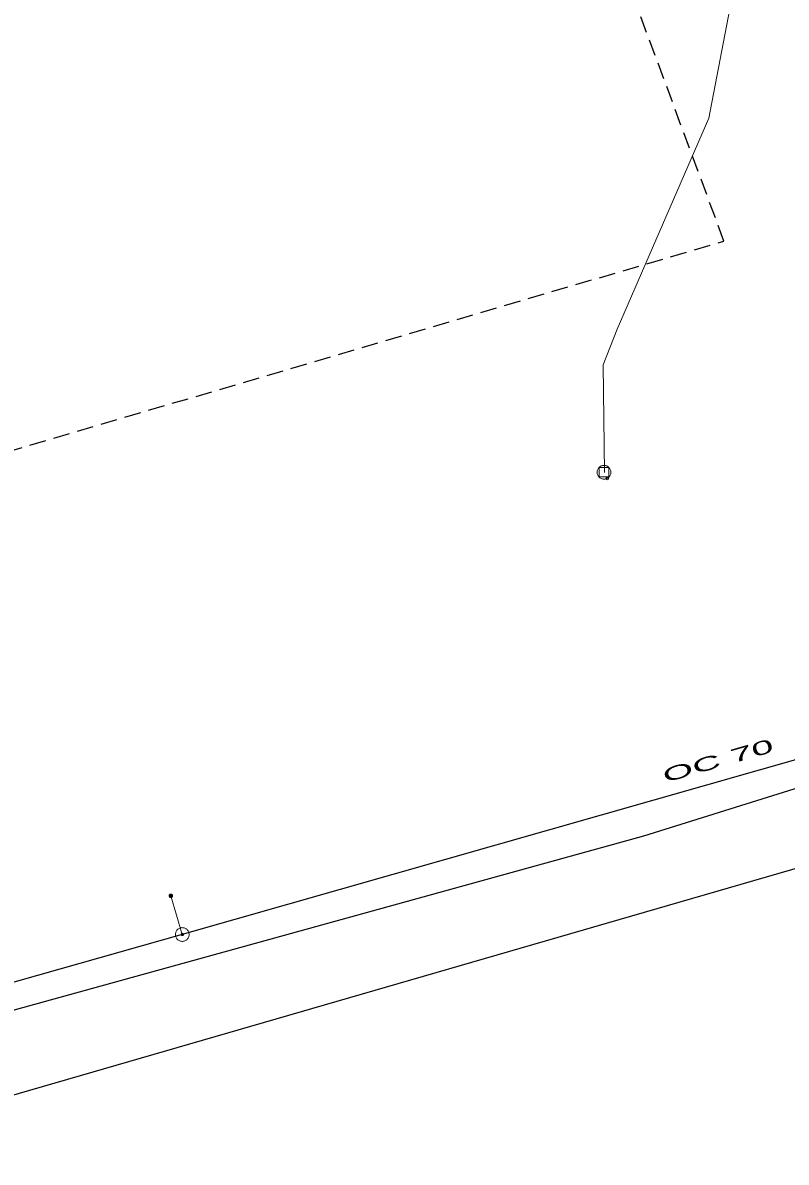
# Model space of a CAD drawing. Extents: x -690254 to -689100, y -975264 to -974703.
# Drawn here: x -689747.9 to -689692.3, y -975075.2 to -974992.3 of the extents above; entities that cross this region are included whole.
import ezdxf

# ---------------------------------------------------------------- set-up
doc = ezdxf.new("R2010")
doc.units = 0
doc.header["$LTSCALE"] = 0.4
doc.header["$PDMODE"] = 32
doc.header["$PDSIZE"] = 0.2
doc.linetypes.add('MEDIUM_DASHED', pattern=[4.5, 3, -1.5])
for name, color, linetype, lineweight in [('1', 7, 'Continuous', 13), ('11', 7, 'Continuous', 13), ('14', 7, 'Continuous', 13), ('17', 7, 'Continuous', 25), ('22', 7, 'Continuous', 13), ('47', 7, 'Continuous', 13), ('63', 7, 'MEDIUM_DASHED', 25), ('9', 7, 'Continuous', 13)]:
    doc.layers.add(name, color=color, linetype=linetype, lineweight=lineweight)

msp = doc.modelspace()

# ---------------------------------------------------------------- linework, layer by layer
at = {"layer": '11'}
msp.add_lwpolyline([(-689705.559, -975025.01), (-689705.649, -975017.17), (-689704.62, -975014.579), (-689697.949, -974999.219), (-689696.3, -974990.64)], dxfattribs=at)
at = {"layer": '14'}
msp.add_line((-689736.277, -975058.649), (-689737.109, -975055.829), dxfattribs=at)
at = {"layer": '17'}
for p, q in [((-689660.67, -975037.094), (-689736.277, -975058.649)), ((-689736.277, -975058.649), (-689791.401, -975074.243))]:
    msp.add_line(p, q, dxfattribs=at)
for points in [[(-689651.896, -975035.605), (-689702.719, -975051.484), (-689800.052, -975078.399), (-689860.597, -975095.177), (-689913.514, -975110.178), (-689937.55, -975117.079), (-689948.793, -975119.833), (-689957.109, -975122.39), (-689986.109, -975129.956), (-690002.122, -975134.99), (-690005.949, -975136.193), (-690003.879, -975142.529), (-690036.781, -975151.448), (-690069.227, -975161.229), (-690080.424, -975165.129), (-690111.773, -975174.27), (-690115.204, -975175.288), (-690118.142, -975167.265)], [(-689654.548, -975043.14), (-689663.456, -975045.689), (-689770.531, -975076.689), (-689789.368, -975082.372), (-689795.659, -975083.946), (-689875.347, -975106.869), (-689899.317, -975114.153), (-689955.443, -975128.986), (-689982.052, -975137.931), (-690059.236, -975159.265)]]:
    msp.add_lwpolyline(points, dxfattribs=at)
at = {"layer": '22'}
for points in [[(-689705.09, -975025.001), (-689705.092, -975024.949), (-689705.102, -975024.896), (-689705.115, -975024.846), (-689705.133, -975024.797), (-689705.157, -975024.751), (-689705.187, -975024.706), (-689705.219, -975024.666), (-689705.257, -975024.63), (-689705.296, -975024.596), (-689705.34, -975024.567), (-689705.388, -975024.543), (-689705.436, -975024.526), (-689705.486, -975024.511), (-689705.539, -975024.503), (-689705.59, -975024.502), (-689705.642, -975024.504), (-689705.695, -975024.513), (-689705.746, -975024.526), (-689705.794, -975024.544), (-689705.84, -975024.569), (-689705.884, -975024.598), (-689705.925, -975024.63), (-689705.962, -975024.668), (-689705.995, -975024.707), (-689706.023, -975024.751), (-689706.047, -975024.799), (-689706.066, -975024.847), (-689706.08, -975024.897), (-689706.086, -975024.95), (-689706.089, -975025.001), (-689706.086, -975025.053), (-689706.078, -975025.106), (-689706.066, -975025.157), (-689706.046, -975025.205), (-689706.022, -975025.251), (-689705.994, -975025.296), (-689705.961, -975025.336), (-689705.924, -975025.373), (-689705.883, -975025.406), (-689705.84, -975025.435), (-689705.792, -975025.458), (-689705.744, -975025.477), (-689705.693, -975025.491), (-689705.641, -975025.498), (-689705.59, -975025.501), (-689705.538, -975025.498), (-689705.485, -975025.489), (-689705.435, -975025.477), (-689705.386, -975025.457), (-689705.339, -975025.433), (-689705.295, -975025.405), (-689705.255, -975025.373), (-689705.219, -975025.335), (-689705.185, -975025.295), (-689705.156, -975025.251), (-689705.132, -975025.203), (-689705.114, -975025.156), (-689705.1, -975025.105), (-689705.092, -975025.052)], [(-689705.94, -975024.651), (-689705.232, -975024.65), (-689705.231, -975025.344), (-689705.94, -975025.344)]]:
    msp.add_lwpolyline(points, close=True, dxfattribs=at)
msp.add_point((-689705.365, -975025.449), dxfattribs=at)
at = {"layer": '47'}
for points in [[(-689735.794, -975058.519), (-689735.81, -975058.47), (-689735.831, -975058.422), (-689735.858, -975058.377), (-689735.888, -975058.334), (-689735.923, -975058.295), (-689735.962, -975058.26), (-689736.005, -975058.23), (-689736.05, -975058.204), (-689736.097, -975058.182), (-689736.147, -975058.166), (-689736.199, -975058.155), (-689736.251, -975058.15), (-689736.303, -975058.149), (-689736.355, -975058.155), (-689736.406, -975058.166), (-689736.455, -975058.182), (-689736.503, -975058.203), (-689736.549, -975058.23), (-689736.591, -975058.26), (-689736.63, -975058.295), (-689736.665, -975058.334), (-689736.696, -975058.377), (-689736.722, -975058.422), (-689736.744, -975058.469), (-689736.759, -975058.519), (-689736.77, -975058.571), (-689736.776, -975058.623), (-689736.776, -975058.675), (-689736.77, -975058.727), (-689736.759, -975058.778), (-689736.743, -975058.827), (-689736.722, -975058.875), (-689736.696, -975058.921), (-689736.665, -975058.963), (-689736.63, -975059.002), (-689736.592, -975059.037), (-689736.549, -975059.068), (-689736.504, -975059.095), (-689736.456, -975059.116), (-689736.406, -975059.131), (-689736.354, -975059.142), (-689736.303, -975059.148), (-689736.25, -975059.148), (-689736.198, -975059.142), (-689736.147, -975059.131), (-689736.098, -975059.115), (-689736.05, -975059.094), (-689736.005, -975059.068), (-689735.962, -975059.037), (-689735.923, -975059.002), (-689735.888, -975058.964), (-689735.858, -975058.921), (-689735.831, -975058.876), (-689735.81, -975058.828), (-689735.794, -975058.778), (-689735.783, -975058.726), (-689735.778, -975058.675), (-689735.777, -975058.622), (-689735.783, -975058.57)], [(-689736.197, -975058.627), (-689736.2, -975058.619), (-689736.204, -975058.611), (-689736.208, -975058.604), (-689736.213, -975058.597), (-689736.219, -975058.591), (-689736.225, -975058.585), (-689736.232, -975058.58), (-689736.239, -975058.575), (-689736.247, -975058.572), (-689736.255, -975058.569), (-689736.264, -975058.568), (-689736.273, -975058.567), (-689736.281, -975058.567), (-689736.289, -975058.567), (-689736.298, -975058.569), (-689736.306, -975058.572), (-689736.314, -975058.576), (-689736.321, -975058.58), (-689736.328, -975058.585), (-689736.334, -975058.591), (-689736.34, -975058.597), (-689736.345, -975058.604), (-689736.35, -975058.611), (-689736.354, -975058.619), (-689736.356, -975058.627), (-689736.357, -975058.636), (-689736.358, -975058.645), (-689736.358, -975058.653), (-689736.358, -975058.661), (-689736.356, -975058.67), (-689736.353, -975058.678), (-689736.349, -975058.686), (-689736.345, -975058.693), (-689736.34, -975058.7), (-689736.334, -975058.706), (-689736.329, -975058.712), (-689736.321, -975058.717), (-689736.314, -975058.722), (-689736.306, -975058.726), (-689736.298, -975058.728), (-689736.289, -975058.729), (-689736.28, -975058.73), (-689736.272, -975058.73), (-689736.264, -975058.73), (-689736.255, -975058.728), (-689736.247, -975058.725), (-689736.239, -975058.721), (-689736.232, -975058.717), (-689736.225, -975058.712), (-689736.219, -975058.706), (-689736.213, -975058.701), (-689736.208, -975058.693), (-689736.203, -975058.686), (-689736.2, -975058.678), (-689736.197, -975058.67), (-689736.196, -975058.661), (-689736.195, -975058.652), (-689736.195, -975058.644), (-689736.195, -975058.636)]]:
    msp.add_lwpolyline(points, close=True, dxfattribs=at)
at = {"layer": '63'}
msp.add_lwpolyline([(-690175.832, -975238.167), (-690201.511, -975156.663), (-690201.511, -975156.663), (-689696.859, -975008.171), (-689696.859, -975008.171), (-689730.354, -974917.735), (-689730.354, -974917.735), (-689127.452, -974763.66), (-689127.452, -974763.66), (-689118.52, -974838.465), (-689118.52, -974838.465), (-689624.288, -974970.21), (-689624.288, -974970.21), (-689593.026, -975070.694), (-689593.026, -975070.694)], close=True, dxfattribs=at)
at = {"layer": '9'}
for points in [[(-689737.235, -975055.829), (-689737.235, -975055.842), (-689737.233, -975055.855), (-689737.23, -975055.868), (-689737.225, -975055.88), (-689737.219, -975055.892), (-689737.212, -975055.903), (-689737.204, -975055.913), (-689737.194, -975055.923), (-689737.184, -975055.931), (-689737.173, -975055.938), (-689737.161, -975055.944), (-689737.149, -975055.949), (-689737.136, -975055.952), (-689737.123, -975055.954), (-689737.11, -975055.956), (-689737.097, -975055.955), (-689737.084, -975055.953), (-689737.071, -975055.95), (-689737.059, -975055.945), (-689737.047, -975055.939), (-689737.036, -975055.932), (-689737.026, -975055.924), (-689737.016, -975055.914), (-689737.008, -975055.904), (-689737.001, -975055.893), (-689736.995, -975055.881), (-689736.99, -975055.869), (-689736.987, -975055.856), (-689736.985, -975055.843), (-689736.983, -975055.83), (-689736.984, -975055.817), (-689736.986, -975055.804), (-689736.989, -975055.791), (-689736.994, -975055.779), (-689737, -975055.767), (-689737.007, -975055.756), (-689737.015, -975055.746), (-689737.025, -975055.736), (-689737.035, -975055.728), (-689737.046, -975055.721), (-689737.058, -975055.715), (-689737.07, -975055.71), (-689737.083, -975055.707), (-689737.096, -975055.705), (-689737.109, -975055.704), (-689737.122, -975055.704), (-689737.135, -975055.706), (-689737.148, -975055.709), (-689737.16, -975055.714), (-689737.172, -975055.72), (-689737.183, -975055.727), (-689737.193, -975055.735), (-689737.203, -975055.745), (-689737.211, -975055.755), (-689737.218, -975055.766), (-689737.224, -975055.778), (-689737.229, -975055.79), (-689737.232, -975055.803), (-689737.234, -975055.816)], [(-689737.215, -975055.829), (-689737.216, -975055.84), (-689737.214, -975055.851), (-689737.211, -975055.862), (-689737.207, -975055.872), (-689737.202, -975055.882), (-689737.196, -975055.891), (-689737.189, -975055.9), (-689737.181, -975055.908), (-689737.172, -975055.915), (-689737.163, -975055.921), (-689737.153, -975055.926), (-689737.143, -975055.93), (-689737.132, -975055.933), (-689737.121, -975055.936), (-689737.11, -975055.936), (-689737.099, -975055.936), (-689737.088, -975055.934), (-689737.077, -975055.931), (-689737.067, -975055.927), (-689737.057, -975055.922), (-689737.048, -975055.916), (-689737.039, -975055.909), (-689737.031, -975055.901), (-689737.024, -975055.892), (-689737.018, -975055.883), (-689737.013, -975055.873), (-689737.009, -975055.863), (-689737.006, -975055.852), (-689737.004, -975055.841), (-689737.003, -975055.83), (-689737.003, -975055.819), (-689737.005, -975055.808), (-689737.008, -975055.797), (-689737.012, -975055.787), (-689737.017, -975055.777), (-689737.023, -975055.768), (-689737.03, -975055.759), (-689737.038, -975055.751), (-689737.047, -975055.744), (-689737.056, -975055.738), (-689737.066, -975055.733), (-689737.076, -975055.729), (-689737.087, -975055.726), (-689737.098, -975055.724), (-689737.109, -975055.724), (-689737.12, -975055.723), (-689737.131, -975055.725), (-689737.142, -975055.728), (-689737.152, -975055.732), (-689737.162, -975055.737), (-689737.171, -975055.743), (-689737.18, -975055.75), (-689737.188, -975055.758), (-689737.195, -975055.767), (-689737.201, -975055.776), (-689737.206, -975055.786), (-689737.21, -975055.796), (-689737.213, -975055.807), (-689737.215, -975055.818)], [(-689737.196, -975055.829), (-689737.196, -975055.838), (-689737.195, -975055.847), (-689737.192, -975055.856), (-689737.189, -975055.864), (-689737.185, -975055.872), (-689737.18, -975055.88), (-689737.174, -975055.887), (-689737.168, -975055.893), (-689737.161, -975055.899), (-689737.153, -975055.904), (-689737.145, -975055.908), (-689737.137, -975055.911), (-689737.128, -975055.914), (-689737.119, -975055.915), (-689737.11, -975055.917), (-689737.101, -975055.916), (-689737.092, -975055.915), (-689737.083, -975055.912), (-689737.075, -975055.909), (-689737.067, -975055.905), (-689737.059, -975055.9), (-689737.052, -975055.894), (-689737.046, -975055.888), (-689737.04, -975055.881), (-689737.035, -975055.873), (-689737.031, -975055.865), (-689737.028, -975055.857), (-689737.025, -975055.848), (-689737.024, -975055.839), (-689737.022, -975055.83), (-689737.023, -975055.821), (-689737.024, -975055.812), (-689737.027, -975055.803), (-689737.03, -975055.795), (-689737.034, -975055.787), (-689737.039, -975055.779), (-689737.045, -975055.772), (-689737.051, -975055.766), (-689737.058, -975055.76), (-689737.066, -975055.755), (-689737.074, -975055.751), (-689737.082, -975055.748), (-689737.091, -975055.745), (-689737.1, -975055.744), (-689737.109, -975055.743), (-689737.118, -975055.743), (-689737.127, -975055.744), (-689737.136, -975055.747), (-689737.144, -975055.75), (-689737.152, -975055.754), (-689737.16, -975055.759), (-689737.167, -975055.765), (-689737.173, -975055.771), (-689737.179, -975055.778), (-689737.184, -975055.786), (-689737.188, -975055.794), (-689737.191, -975055.802), (-689737.194, -975055.811), (-689737.195, -975055.82)], [(-689737.176, -975055.829), (-689737.176, -975055.836), (-689737.175, -975055.843), (-689737.174, -975055.85), (-689737.171, -975055.856), (-689737.168, -975055.862), (-689737.164, -975055.868), (-689737.16, -975055.874), (-689737.155, -975055.879), (-689737.149, -975055.883), (-689737.143, -975055.887), (-689737.137, -975055.89), (-689737.131, -975055.893), (-689737.124, -975055.894), (-689737.117, -975055.897), (-689737.11, -975055.897), (-689737.103, -975055.897), (-689737.096, -975055.895), (-689737.089, -975055.894), (-689737.083, -975055.891), (-689737.076, -975055.888), (-689737.071, -975055.884), (-689737.065, -975055.88), (-689737.06, -975055.875), (-689737.056, -975055.869), (-689737.052, -975055.863), (-689737.049, -975055.857), (-689737.046, -975055.851), (-689737.044, -975055.844), (-689737.043, -975055.837), (-689737.042, -975055.83), (-689737.042, -975055.823), (-689737.043, -975055.816), (-689737.045, -975055.809), (-689737.048, -975055.803), (-689737.051, -975055.796), (-689737.055, -975055.791), (-689737.059, -975055.785), (-689737.064, -975055.78), (-689737.07, -975055.776), (-689737.075, -975055.772), (-689737.082, -975055.769), (-689737.088, -975055.766), (-689737.095, -975055.764), (-689737.102, -975055.763), (-689737.109, -975055.763), (-689737.116, -975055.763), (-689737.123, -975055.763), (-689737.13, -975055.765), (-689737.136, -975055.768), (-689737.142, -975055.771), (-689737.148, -975055.775), (-689737.154, -975055.779), (-689737.159, -975055.784), (-689737.163, -975055.79), (-689737.167, -975055.795), (-689737.17, -975055.802), (-689737.173, -975055.808), (-689737.174, -975055.815), (-689737.176, -975055.822)], [(-689737.156, -975055.829), (-689737.156, -975055.834), (-689737.156, -975055.839), (-689737.155, -975055.844), (-689737.153, -975055.848), (-689737.151, -975055.853), (-689737.148, -975055.857), (-689737.145, -975055.86), (-689737.141, -975055.864), (-689737.138, -975055.867), (-689737.134, -975055.87), (-689737.129, -975055.872), (-689737.125, -975055.874), (-689737.12, -975055.875), (-689737.115, -975055.877), (-689737.11, -975055.877), (-689737.105, -975055.877), (-689737.1, -975055.876), (-689737.095, -975055.875), (-689737.091, -975055.873), (-689737.086, -975055.871), (-689737.082, -975055.868), (-689737.078, -975055.865), (-689737.075, -975055.861), (-689737.072, -975055.858), (-689737.069, -975055.854), (-689737.067, -975055.849), (-689737.065, -975055.845), (-689737.064, -975055.84), (-689737.063, -975055.835), (-689737.062, -975055.83), (-689737.062, -975055.825), (-689737.063, -975055.82), (-689737.064, -975055.815), (-689737.066, -975055.811), (-689737.068, -975055.806), (-689737.071, -975055.802), (-689737.074, -975055.798), (-689737.077, -975055.795), (-689737.081, -975055.792), (-689737.085, -975055.789), (-689737.09, -975055.787), (-689737.094, -975055.785), (-689737.099, -975055.784), (-689737.104, -975055.783), (-689737.109, -975055.783), (-689737.114, -975055.783), (-689737.119, -975055.784), (-689737.124, -975055.784), (-689737.128, -975055.786), (-689737.133, -975055.788), (-689737.137, -975055.791), (-689737.14, -975055.794), (-689737.144, -975055.797), (-689737.147, -975055.801), (-689737.15, -975055.805), (-689737.152, -975055.81), (-689737.154, -975055.814), (-689737.155, -975055.819), (-689737.156, -975055.824)], [(-689737.136, -975055.829), (-689737.136, -975055.832), (-689737.137, -975055.835), (-689737.136, -975055.837), (-689737.135, -975055.84), (-689737.134, -975055.843), (-689737.132, -975055.845), (-689737.13, -975055.847), (-689737.128, -975055.849), (-689737.126, -975055.851), (-689737.124, -975055.853), (-689737.121, -975055.855), (-689737.118, -975055.856), (-689737.116, -975055.856), (-689737.113, -975055.857), (-689737.11, -975055.857), (-689737.107, -975055.857), (-689737.104, -975055.857), (-689737.101, -975055.856), (-689737.099, -975055.855), (-689737.096, -975055.854), (-689737.094, -975055.852), (-689737.091, -975055.85), (-689737.089, -975055.848), (-689737.088, -975055.846), (-689737.086, -975055.844), (-689737.085, -975055.841), (-689737.083, -975055.838), (-689737.083, -975055.836), (-689737.082, -975055.833), (-689737.081, -975055.83), (-689737.082, -975055.827), (-689737.082, -975055.824), (-689737.083, -975055.821), (-689737.084, -975055.819), (-689737.085, -975055.816), (-689737.087, -975055.814), (-689737.088, -975055.811), (-689737.09, -975055.809), (-689737.093, -975055.808), (-689737.095, -975055.806), (-689737.098, -975055.805), (-689737.1, -975055.804), (-689737.103, -975055.803), (-689737.106, -975055.803), (-689737.109, -975055.802), (-689737.112, -975055.803), (-689737.115, -975055.802), (-689737.117, -975055.804), (-689737.12, -975055.804), (-689737.123, -975055.805), (-689737.125, -975055.807), (-689737.127, -975055.808), (-689737.129, -975055.81), (-689737.131, -975055.813), (-689737.133, -975055.815), (-689737.134, -975055.818), (-689737.135, -975055.82), (-689737.136, -975055.823), (-689737.136, -975055.826)], [(-689737.117, -975055.829), (-689737.117, -975055.831), (-689737.117, -975055.831), (-689737.116, -975055.831), (-689737.116, -975055.833), (-689737.117, -975055.834), (-689737.115, -975055.834), (-689737.115, -975055.834), (-689737.115, -975055.836), (-689737.115, -975055.836), (-689737.114, -975055.837), (-689737.112, -975055.837), (-689737.112, -975055.837), (-689737.112, -975055.838), (-689737.11, -975055.838), (-689737.11, -975055.838), (-689737.109, -975055.838), (-689737.108, -975055.838), (-689737.108, -975055.837), (-689737.107, -975055.837), (-689737.105, -975055.837), (-689737.105, -975055.836), (-689737.105, -975055.836), (-689737.104, -975055.835), (-689737.104, -975055.835), (-689737.102, -975055.834), (-689737.102, -975055.833), (-689737.101, -975055.832), (-689737.101, -975055.832), (-689737.101, -975055.831), (-689737.101, -975055.83), (-689737.101, -975055.829), (-689737.101, -975055.828), (-689737.101, -975055.828), (-689737.102, -975055.827), (-689737.102, -975055.826), (-689737.103, -975055.825), (-689737.103, -975055.825), (-689737.104, -975055.824), (-689737.104, -975055.824), (-689737.105, -975055.823), (-689737.106, -975055.823), (-689737.107, -975055.822), (-689737.107, -975055.822), (-689737.108, -975055.822), (-689737.109, -975055.822), (-689737.11, -975055.822), (-689737.111, -975055.822), (-689737.111, -975055.822), (-689737.112, -975055.823), (-689737.113, -975055.822), (-689737.114, -975055.824), (-689737.114, -975055.824), (-689737.115, -975055.824), (-689737.115, -975055.824), (-689737.116, -975055.826), (-689737.116, -975055.827), (-689737.116, -975055.828), (-689737.117, -975055.828), (-689737.117, -975055.829)]]:
    msp.add_lwpolyline(points, close=True, dxfattribs=at)

# ---------------------------------------------------------------- texts
at = {"layer": '1', "width": 2.15}
msp.add_text('OC 70 ', height=1, rotation=16, dxfattribs=at).set_placement((-689701.147, -975047.609))

doc.saveas('drawing.dxf')
